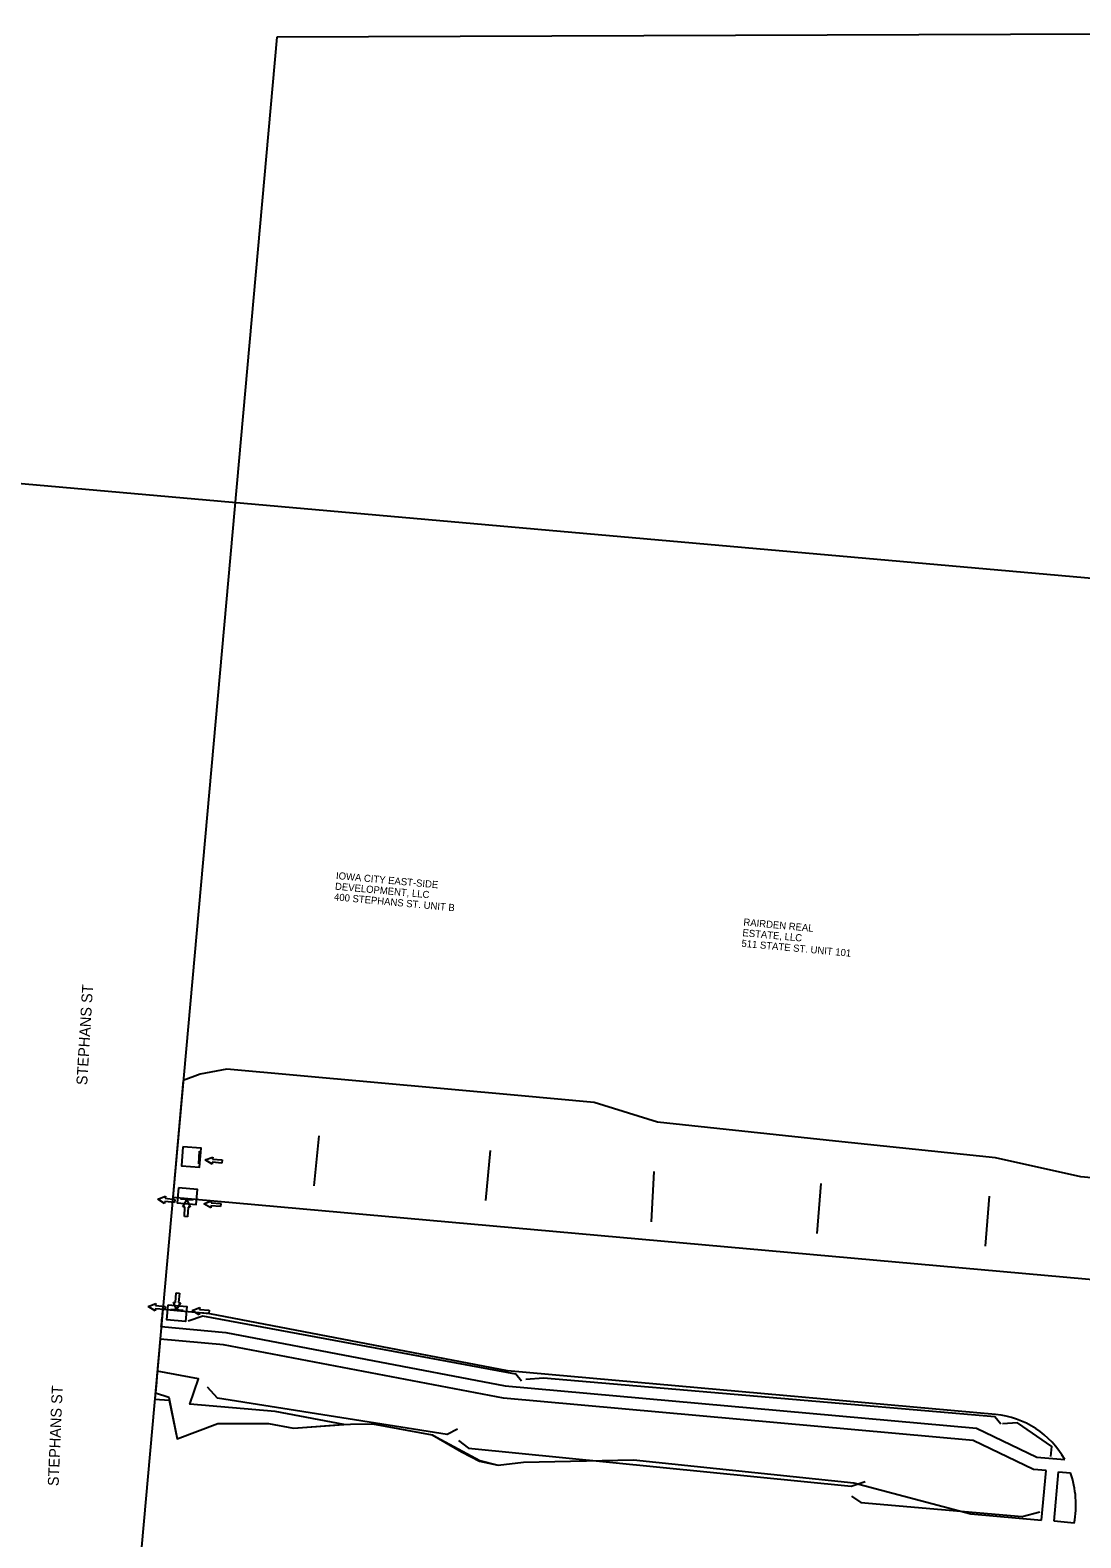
# Model space of a CAD drawing. Extents: x 20499990 to 20504504, y 7953381 to 7954379.
# Drawn here: x 20501741 to 20502160, y 7953779 to 7954379 of the extents above; entities that cross this region are included whole.
import ezdxf

# ---------------------------------------------------------------- set-up
doc = ezdxf.new("R2010")
doc.units = 0
for name, color, linetype in [('ClearGrub', 7, 'Continuous'), ('Draft_DNC', 7, 'Continuous'), ('dsnCellElements', 7, 'Continuous'), ('ErosionControl', 7, 'Continuous'), ('NamedBoundary', 7, 'Continuous'), ('rowdsnSymbolsProposed', 7, 'Continuous'), ('Seeding', 7, 'Continuous'), ('Text', 7, 'Continuous')]:
    doc.layers.add(name, color=color, linetype=linetype)

msp = doc.modelspace()

# ---------------------------------------------------------------- linework, layer by layer
at = {"layer": 'ClearGrub'}
msp.add_lwpolyline([(20501791.28, 7953836.36), (20501796.6, 7953834.6), (20501800, 7953817.95), (20501816.11, 7953824.15), (20501836.38, 7953824.12), (20501846.25, 7953822.23), (20501863.95, 7953823.64), (20501866.29, 7953823.76), (20501838.99, 7953828.85), (20501805.05, 7953831.87), (20501808.46, 7953841.89), (20501792.05, 7953844.92), (20501791.67, 7953840.62), (20501791.28, 7953836.36)], dxfattribs=at)
at = {"layer": 'Draft_DNC'}
msp.add_lwpolyline([(20501839.61, 7954376.08), (20501750.51, 7953380.96), (20502519.96, 7953384.14), (20502606.52, 7954378.84)], close=True, dxfattribs=at)
at = {"layer": 'dsnCellElements'}
for p, q in [((20501811.13, 7953929.04), (20501814.11, 7953930.2)), ((20501813.85, 7953927.35), (20501811.13, 7953929.04)), ((20501813.92, 7953928.14), (20501813.85, 7953927.35)), ((20501817.72, 7953927.79), (20501813.92, 7953928.14)), ((20501814.11, 7953930.2), (20501814.04, 7953929.41)), ((20501814.04, 7953929.41), (20501817.84, 7953929.05)), ((20501817.84, 7953929.05), (20501817.72, 7953927.79)), ((20501792.28, 7953913.45), (20501795.29, 7953914.56)), ((20501794.97, 7953911.72), (20501792.28, 7953913.45)), ((20501795.06, 7953912.51), (20501794.97, 7953911.72)), ((20501798.85, 7953912.09), (20501795.06, 7953912.51)), ((20501795.29, 7953914.56), (20501795.2, 7953913.77)), ((20501795.2, 7953913.77), (20501798.99, 7953913.35)), ((20501798.99, 7953913.35), (20501798.85, 7953912.09)), ((20501802.26, 7953910.38), (20501803.86, 7953913.16)), ((20501803.05, 7953910.34), (20501802.26, 7953910.38)), ((20501802.83, 7953906.53), (20501803.05, 7953910.34)), ((20501803.86, 7953913.16), (20501805.11, 7953910.22)), ((20501804.32, 7953910.26), (20501804.1, 7953906.45)), ((20501805.11, 7953910.22), (20501804.32, 7953910.26)), ((20501810.58, 7953911.6), (20501813.54, 7953912.81)), ((20501813.33, 7953909.96), (20501810.58, 7953911.6)), ((20501813.38, 7953910.75), (20501813.33, 7953909.96)), ((20501817.19, 7953910.46), (20501813.38, 7953910.75)), ((20501813.54, 7953912.81), (20501813.48, 7953912.02)), ((20501813.48, 7953912.02), (20501817.29, 7953911.73)), ((20501817.29, 7953911.73), (20501817.19, 7953910.46)), ((20501804.1, 7953906.45), (20501802.83, 7953906.53)), ((20501799.27, 7953872.34), (20501799.58, 7953876.14)), ((20501799.27, 7953872.34), (20501799.58, 7953876.14)), ((20501799.58, 7953876.14), (20501800.85, 7953876.04)), ((20501799.58, 7953876.14), (20501800.85, 7953876.04)), ((20501800.85, 7953876.04), (20501800.54, 7953872.24)), ((20501800.85, 7953876.04), (20501800.54, 7953872.24)), ((20501788.43, 7953870.69), (20501791.41, 7953871.87)), ((20501788.43, 7953870.69), (20501791.41, 7953871.87)), ((20501791.16, 7953869.02), (20501788.43, 7953870.69)), ((20501791.16, 7953869.02), (20501788.43, 7953870.69)), ((20501791.23, 7953869.81), (20501791.16, 7953869.02)), ((20501791.23, 7953869.81), (20501791.16, 7953869.02)), ((20501795.03, 7953869.49), (20501791.23, 7953869.81)), ((20501795.03, 7953869.49), (20501791.23, 7953869.81)), ((20501791.41, 7953871.87), (20501791.34, 7953871.08)), ((20501791.41, 7953871.87), (20501791.34, 7953871.08)), ((20501791.34, 7953871.08), (20501795.14, 7953870.75)), ((20501791.34, 7953871.08), (20501795.14, 7953870.75)), ((20501795.14, 7953870.75), (20501795.03, 7953869.49)), ((20501795.14, 7953870.75), (20501795.03, 7953869.49)), ((20501799.67, 7953869.44), (20501798.48, 7953872.41)), ((20501798.48, 7953872.41), (20501799.27, 7953872.34)), ((20501799.67, 7953869.44), (20501798.48, 7953872.41)), ((20501798.48, 7953872.41), (20501799.27, 7953872.34)), ((20501801.33, 7953872.17), (20501799.67, 7953869.44)), ((20501801.33, 7953872.17), (20501799.67, 7953869.44)), ((20501800.54, 7953872.24), (20501801.33, 7953872.17)), ((20501800.54, 7953872.24), (20501801.33, 7953872.17)), ((20501805.97, 7953869.06), (20501808.93, 7953870.28)), ((20501805.97, 7953869.06), (20501808.93, 7953870.28)), ((20501808.72, 7953867.42), (20501805.97, 7953869.06)), ((20501808.72, 7953867.42), (20501805.97, 7953869.06)), ((20501808.78, 7953868.21), (20501808.72, 7953867.42)), ((20501808.78, 7953868.21), (20501808.72, 7953867.42)), ((20501812.58, 7953867.93), (20501808.78, 7953868.21)), ((20501812.58, 7953867.93), (20501808.78, 7953868.21)), ((20501808.93, 7953870.28), (20501808.87, 7953869.48)), ((20501808.93, 7953870.28), (20501808.87, 7953869.48)), ((20501808.87, 7953869.48), (20501812.68, 7953869.2)), ((20501808.87, 7953869.48), (20501812.68, 7953869.2)), ((20501812.68, 7953869.2), (20501812.58, 7953867.93)), ((20501812.68, 7953869.2), (20501812.58, 7953867.93))]:
    msp.add_line(p, q, dxfattribs=at)
at = {"layer": 'ErosionControl'}
for p, q in [((20501854.57, 7953918.76), (20501856.53, 7953938.67)), ((20501808.77, 7953932.52), (20501808.5, 7953927.53)), ((20501922.91, 7953912.93), (20501924.68, 7953932.85)), ((20501988.87, 7953904.45), (20501989.92, 7953924.42)), ((20502054.83, 7953899.76), (20502056.43, 7953919.69)), ((20501806.32, 7953912.99), (20501801.34, 7953913.44)), ((20502121.81, 7953894.72), (20502123.39, 7953914.65)), ((20501797.42, 7953869.61), (20501802.4, 7953869.17))]:
    msp.add_line(p, q, dxfattribs=at)
for points in [[(20501802.28, 7953934.31), (20501801.68, 7953926.75), (20501808.91, 7953926.17), (20501809.51, 7953933.74)], [(20501800.46, 7953917.94), (20501799.99, 7953911.96), (20501807.53, 7953911.36), (20501808.01, 7953917.34)], [(20501796.4, 7953871.3), (20501803.75, 7953870.64), (20501803.22, 7953864.67), (20501795.87, 7953865.32)]]:
    msp.add_lwpolyline(points, close=True, dxfattribs=at)
for points in [[(20501937.06, 7953840.98), (20501934.78, 7953843.8), (20501810.19, 7953866.88), (20501804.39, 7953864.79)], [(20501911.64, 7953821.87), (20501907.46, 7953819.68), (20501816.05, 7953834.24), (20501812.05, 7953838.62)], [(20502127.93, 7953823.91), (20502125.5, 7953826.72), (20501945.85, 7953842.17), (20501938.72, 7953841.58)], [(20502147.76, 7953810.92), (20502148.25, 7953815.01), (20502134.52, 7953824.32), (20502128.63, 7953824.02)], [(20501911.92, 7953817.4), (20501915.94, 7953814.28), (20502068.27, 7953799.11), (20502073.92, 7953801.04)], [(20502068.45, 7953795.22), (20502072.13, 7953792.72), (20502136.46, 7953787.13), (20502143.47, 7953788.91)]]:
    msp.add_lwpolyline(points, dxfattribs=at)
at = {"layer": 'NamedBoundary'}
msp.add_lwpolyline([(20501724.26, 7954199.37), (20501671.43, 7953601.7), (20502608.28, 7953518.89), (20502661.11, 7954116.56)], close=True, dxfattribs=at)
at = {"layer": 'rowdsnSymbolsProposed'}
for p, q in [((20501802.41, 7953960.63), (20501798.26, 7953914.21)), ((20501812.97, 7953867.72), (20501794.26, 7953869.55)), ((20501931.42, 7953845.06), (20501812.97, 7953867.72)), ((20501793.64, 7953862.7), (20501819.3, 7953860.4)), ((20501793.2, 7953857.73), (20501792.5, 7953849.93)), ((20501818.47, 7953855.47), (20501793.2, 7953857.73)), ((20501929.9, 7953834.16), (20501818.47, 7953855.47)), ((20501819.3, 7953860.4), (20501930.59, 7953839.11)), ((20501792.5, 7953849.93), (20501791.06, 7953833.84)), ((20502125.82, 7953827.66), (20501931.42, 7953845.06)), ((20502144.15, 7953785.64), (20502145.91, 7953805.37)), ((20502149.13, 7953785.2), (20502150.89, 7953804.93)), ((20502150.89, 7953804.93), (20502155.68, 7953804.5)), ((20502157.08, 7953784.49), (20502149.13, 7953785.2))]:
    msp.add_line(p, q, dxfattribs=at)
for points in [[(20502518.94, 7953887.24), (20502474.75, 7953883.95), (20502463.6, 7953869.27), (20502243.87, 7953890.12), (20502199.22, 7953918.64), (20502159.71, 7953922.3), (20502125.82, 7953929.86), (20502062.04, 7953936.51), (20501991.17, 7953944.07), (20501966, 7953951.89), (20501935.61, 7953954.65), (20501819.68, 7953965.17), (20501809.17, 7953963.14), (20501802.41, 7953960.63)], [(20501798.26, 7953914.21), (20502204.56, 7953877.83), (20502491.04, 7953852.88)], [(20501930.59, 7953839.11), (20502118.22, 7953822.31), (20502142.28, 7953810.72), (20502153.33, 7953809.73)], [(20501791.06, 7953833.84), (20501796.84, 7953833.43), (20501800, 7953817.95), (20501816.11, 7953824.15), (20501836.38, 7953824.12), (20501846.25, 7953822.23), (20501866.29, 7953823.76), (20501868.99, 7953823.86), (20501877.76, 7953824), (20501901.46, 7953819.55), (20501920.48, 7953809.35), (20501927.77, 7953807.58), (20501937.92, 7953808.76), (20501981.7, 7953809.61), (20502069.41, 7953800.49), (20502116.01, 7953788.16), (20502144.15, 7953785.64)], [(20502145.91, 7953805.37), (20502140.93, 7953805.82), (20502116.87, 7953817.41), (20501929.9, 7953834.16)]]:
    msp.add_lwpolyline(points, dxfattribs=at)
for centre, radius, start, end in [((20501670.81, 7953877.15), 123.68, 353.2906, 356.4761), ((20502122.7, 7953792.8), 35, 28.9311, 84.88337), ((20502118.76, 7953791.86), 39.03, 349.11274, 18.89274)]:
    msp.add_arc(centre, radius, start, end, dxfattribs=at)
at = {"layer": 'Seeding'}
for p, q in [((20501802.41, 7953960.63), (20501798.26, 7953914.21)), ((20501812.97, 7953867.72), (20501794.26, 7953869.55)), ((20501931.42, 7953845.06), (20501812.97, 7953867.72)), ((20501793.64, 7953862.7), (20501819.3, 7953860.4)), ((20501793.2, 7953857.73), (20501792.5, 7953849.93)), ((20501818.47, 7953855.47), (20501793.2, 7953857.73)), ((20501929.9, 7953834.16), (20501818.47, 7953855.47)), ((20501819.3, 7953860.4), (20501930.59, 7953839.11)), ((20501792.5, 7953849.93), (20501791.06, 7953833.84)), ((20502125.82, 7953827.66), (20501931.42, 7953845.06)), ((20502144.15, 7953785.64), (20502145.91, 7953805.37)), ((20502149.13, 7953785.2), (20502150.89, 7953804.93)), ((20502150.89, 7953804.93), (20502155.68, 7953804.5)), ((20502157.08, 7953784.49), (20502149.13, 7953785.2))]:
    msp.add_line(p, q, dxfattribs=at)
for points in [[(20502518.94, 7953887.24), (20502474.75, 7953883.95), (20502463.6, 7953869.27), (20502243.87, 7953890.12), (20502199.22, 7953918.64), (20502159.71, 7953922.3), (20502125.82, 7953929.86), (20502062.04, 7953936.51), (20501991.17, 7953944.07), (20501966, 7953951.89), (20501935.61, 7953954.65), (20501819.68, 7953965.17), (20501809.17, 7953963.14), (20501802.41, 7953960.63)], [(20501798.26, 7953914.21), (20502204.56, 7953877.83), (20502491.04, 7953852.88)], [(20501930.59, 7953839.11), (20502118.22, 7953822.31), (20502142.28, 7953810.72), (20502153.33, 7953809.73)], [(20501791.06, 7953833.84), (20501796.84, 7953833.43), (20501800, 7953817.95), (20501816.11, 7953824.15), (20501836.38, 7953824.12), (20501846.25, 7953822.23), (20501866.29, 7953823.76), (20501868.99, 7953823.86), (20501877.76, 7953824), (20501901.46, 7953819.55), (20501913.18, 7953812.8), (20501920.38, 7953809.16), (20501927.77, 7953807.58), (20501937.92, 7953808.76), (20501981.7, 7953809.61), (20502069.41, 7953800.49), (20502116.01, 7953788.16), (20502144.15, 7953785.64)], [(20502145.91, 7953805.37), (20502140.93, 7953805.82), (20502116.87, 7953817.41), (20501929.9, 7953834.16)]]:
    msp.add_lwpolyline(points, dxfattribs=at)
for centre, radius, start, end in [((20501659.81, 7953878.14), 134.72, 353.42113, 356.34557), ((20502122.7, 7953792.8), 35, 28.9311, 84.88337), ((20502118.76, 7953791.86), 39.03, 349.11274, 18.89274)]:
    msp.add_arc(centre, radius, start, end, dxfattribs=at)

# ---------------------------------------------------------------- texts
at = {"layer": 'Text'}
for s, height, rotation, p in [('IOWA CITY EAST-SIDE', 2.8346, 354.76449, (20501863.1, 7954040.9)), ('DEVELOPMENT, LLC', 2.8346, 354.76449, (20501862.71, 7954036.66)), ('400 STEPHANS ST. UNIT B', 2.8346, 354.76449, (20501862.32, 7954032.43)), ('RAIRDEN REAL ', 2.8346, 354.76449, (20502025.32, 7954022.4)), ('ESTATE, LLC', 2.8346, 354.76449, (20502024.94, 7954018.16)), ('511 STATE ST. UNIT 101', 2.8346, 354.76449, (20502024.55, 7954013.93)), ('STEPHANS ST', 4.32, 86.5716, (20501764.11, 7953958.73)), ('STEPHANS ST', 4.32, 87.61485, (20501752.74, 7953799.11))]:
    msp.add_text(s, height=height, rotation=rotation, dxfattribs=at).set_placement(p)

doc.saveas('drawing.dxf')
